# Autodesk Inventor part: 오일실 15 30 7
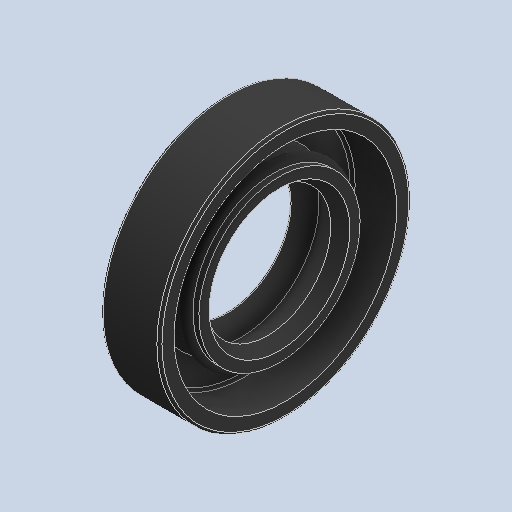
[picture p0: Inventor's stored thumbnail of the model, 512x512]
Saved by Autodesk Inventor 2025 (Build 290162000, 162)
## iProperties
Created: 2024-07
Part Number: 오일실 15 30 7
Material: 고무
Description: 오일-실
Document SubType Name: Modeling
Designer: parkm
Density: 0.93 g/cm^3
Appearance: 기본값
Author: jhkim
Sending System: Autodesk Inventor 2025
Preprocessor: ST-DEVELOPER v20
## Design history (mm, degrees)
feature "Solid1"
node "솔리드1"
